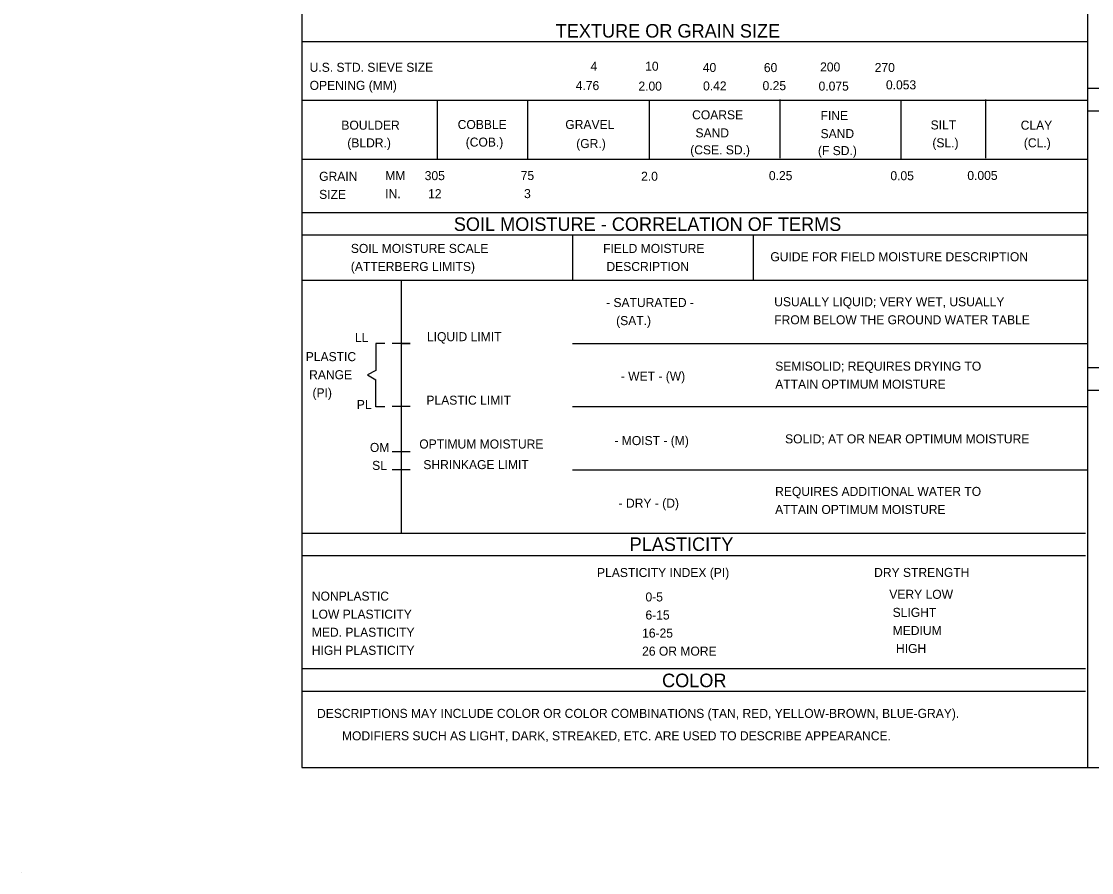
# Model space of a CAD drawing. Extents: x 278710 to 279187, y 171464 to 171625.
# Drawn here: x 278991.9 to 279043.3, y 171480.8 to 171521.6 of the extents above; entities that cross this region are included whole.
import ezdxf

# ---------------------------------------------------------------- set-up
doc = ezdxf.new("R2010")
doc.units = 0
doc.layers.add('Geotech Sheets and Borders Cell', color=7, linetype='Continuous')

msp = doc.modelspace()

# ---------------------------------------------------------------- linework, layer by layer
at = {"layer": 'Geotech Sheets and Borders Cell'}
for p, q in [((279005.33, 171581.203), (279005.33, 171485.806)), ((279043.07, 171566.02), (279043.07, 171485.806)), ((279005.33, 171520.671), (279043.07, 171520.671)), ((279043.07, 171518.437), (279081.678, 171518.437)), ((279005.33, 171517.851), (279043.07, 171517.851)), ((279011.837, 171517.851), (279011.837, 171515.031)), ((279016.175, 171517.851), (279016.175, 171515.031)), ((279022.022, 171517.851), (279022.022, 171515.031)), ((279028.299, 171517.894), (279028.299, 171515.075)), ((279034.108, 171517.851), (279034.108, 171515.031)), ((279038.173, 171517.89), (279038.173, 171515.07)), ((279043.07, 171517.352), (279081.678, 171517.352)), ((279005.33, 171515.031), (279043.07, 171515.031)), ((279005.33, 171512.468), (279043.07, 171512.468)), ((279005.33, 171511.383), (279043.07, 171511.383)), ((279018.344, 171511.383), (279018.344, 171509.214)), ((279027.02, 171511.383), (279027.02, 171509.214)), ((279005.33, 171509.214), (279043.07, 171509.214)), ((279010.101, 171509.214), (279010.101, 171497.068)), ((279010.535, 171506.178), (279009.668, 171506.178)), ((279010.101, 171506.178), (279010.535, 171506.178)), ((279018.344, 171506.178), (279043.07, 171506.178)), ((279121.332, 171505.006), (279043.07, 171505.006)), ((279121.332, 171503.922), (279043.07, 171503.922)), ((279010.535, 171503.141), (279009.668, 171503.141)), ((279018.344, 171503.141), (279043.07, 171503.141)), ((279010.535, 171500.972), (279009.668, 171500.972)), ((279010.535, 171500.104), (279009.668, 171500.104)), ((279018.344, 171500.104), (279043.07, 171500.104)), ((279005.33, 171497.068), (279042.97, 171497.068)), ((279005.33, 171495.983), (279042.97, 171495.983)), ((279005.33, 171490.561), (279042.97, 171490.561)), ((279005.33, 171489.476), (279042.97, 171489.476)), ((279005.33, 171485.806), (279158.027, 171485.806)), ((278991.866, 171480.763), (278991.866, 171480.763))]:
    msp.add_line(p, q, dxfattribs=at)
for points in [[(279009.316, 171506.173), (279008.882, 171506.173), (279008.882, 171504.872)], [(279008.882, 171504.872), (279008.492, 171504.668), (279008.882, 171504.425)], [(279009.316, 171503.124), (279008.882, 171503.124), (279008.882, 171504.425)]]:
    msp.add_lwpolyline(points, dxfattribs=at)

# ---------------------------------------------------------------- texts
for s, height, p in [('TEXTURE OR GRAIN SIZE', 0.6507, (279017.528, 171520.862)), ('U.S. STD. SIEVE SIZE', 0.43381, (279005.711, 171519.218)), ('4    ', 0.4338, (279019.203, 171519.27)), ('10', 0.4338, (279021.827, 171519.27)), (' 40 ', 0.4338, (279024.434, 171519.209)), (' 60   ', 0.4338, (279027.367, 171519.205)), (' 200', 0.4338, (279030.069, 171519.235)), ('   270', 0.4338, (279032.368, 171519.209)), ('OPENING (MM)', 0.43381, (279005.711, 171518.35)), ('4.76   ', 0.4338, (279018.491, 171518.341)), ('2.00', 0.4338, (279021.502, 171518.315)), ('0.42', 0.4338, (279024.608, 171518.324)), ('0.25', 0.4338, (279027.466, 171518.337)), ('0.075', 0.4338, (279030.156, 171518.315)), ('0.053', 0.4338, (279033.392, 171518.376)), ('COARSE', 0.4338, (279024.083, 171516.936)), ('FINE', 0.4338, (279030.251, 171516.901)), ('BOULDER', 0.4338, (279007.234, 171516.437)), ('COBBLE', 0.4338, (279012.821, 171516.472)), ('GRAVEL', 0.4338, (279017.992, 171516.472)), (' SAND', 0.4338, (279024.083, 171516.068)), ('SAND', 0.4338, (279030.251, 171516.033)), ('SILT', 0.4338, (279035.539, 171516.45)), ('CLAY', 0.4338, (279039.864, 171516.437)), ('(BLDR.)', 0.4338, (279007.52, 171515.591)), ('(COB.)', 0.4338, (279013.207, 171515.626)), ('(GR.)', 0.4338, (279018.517, 171515.556)), ('(SL.)', 0.4338, (279035.622, 171515.591)), ('(CL.)', 0.4338, (279040.016, 171515.591)), ('(CSE. SD.)', 0.4338, (279023.992, 171515.253)), ('(F SD.)', 0.4338, (279030.126, 171515.218)), ('GRAIN', 0.4338, (279006.167, 171513.982)), ('MM', 0.4338, (279009.342, 171514.016)), ('305', 0.4338, (279011.238, 171514.016)), ('75', 0.4338, (279015.849, 171514.02)), ('2.0', 0.4338, (279021.632, 171513.986)), ('0.25', 0.4338, (279027.77, 171514.016)), ('0.05', 0.4338, (279033.605, 171514.012)), ('0.005', 0.4338, (279037.301, 171514.025)), ('SIZE', 0.4338, (279006.167, 171513.114)), ('IN.', 0.4338, (279009.342, 171513.149)), (' 12', 0.4338, (279011.238, 171513.149)), (' 3', 0.4338, (279015.849, 171513.153)), ('SOIL MOISTURE - CORRELATION OF TERMS', 0.6507, (279012.635, 171511.578)), ('SOIL MOISTURE SCALE', 0.43381, (279007.69, 171510.52)), ('FIELD MOISTURE', 0.43381, (279019.806, 171510.52)), ('GUIDE FOR FIELD MOISTURE DESCRIPTION', 0.43381, (279027.84, 171510.121)), ('(ATTERBERG LIMITS)', 0.43381, (279007.69, 171509.652)), (' DESCRIPTION', 0.43381, (279019.806, 171509.652)), ('- SATURATED -', 0.43381, (279019.949, 171507.921)), ('USUALLY LIQUID; VERY WET, USUALLY', 0.43381, (279028.026, 171507.96)), ('   (SAT.)', 0.4338, (279019.949, 171507.054)), ('FROM BELOW THE GROUND WATER TABLE', 0.43381, (279028.026, 171507.093)), ('LIQUID LIMIT', 0.43381, (279011.346, 171506.282)), ('LL', 0.4338, (279007.889, 171506.243)), ('PLASTIC', 0.4338, (279005.525, 171505.323)), ('SEMISOLID; REQUIRES DRYING TO', 0.43381, (279028.074, 171504.867)), (' RANGE', 0.4338, (279005.525, 171504.455)), ('- WET - (W)', 0.43381, (279020.656, 171504.386)), ('ATTAIN OPTIMUM MOISTURE', 0.43381, (279028.074, 171504)), ('  (PI)', 0.4338, (279005.525, 171503.588)), ('PLASTIC LIMIT', 0.43381, (279011.32, 171503.232)), ('PL', 0.4338, (279007.976, 171503.024)), ('OPTIMUM MOISTURE', 0.43381, (279010.978, 171501.128)), ('- MOIST - (M)', 0.43381, (279020.348, 171501.293)), ('SOLID; AT OR NEAR OPTIMUM MOISTURE', 0.43381, (279028.547, 171501.375)), ('OM', 0.4338, (279008.605, 171500.963)), ('SL', 0.4338, (279008.713, 171500.1)), ('SHRINKAGE LIMIT', 0.43381, (279011.173, 171500.139)), ('REQUIRES ADDITIONAL WATER TO', 0.43381, (279028.069, 171498.851)), ('- DRY - (D)', 0.43381, (279020.552, 171498.287)), ('ATTAIN OPTIMUM MOISTURE', 0.43381, (279028.069, 171497.983)), ('PLASTICITY', 0.6507, (279021.081, 171496.209)), ('PLASTICITY INDEX (PI)', 0.43381, (279019.515, 171494.955)), ('DRY STRENGTH', 0.43381, (279032.824, 171494.959)), ('NONPLASTIC', 0.4338, (279005.816, 171493.823)), (' 0-5', 0.4338, (279021.68, 171493.784)), ('VERY LOW', 0.4338, (279033.553, 171493.91)), ('LOW PLASTICITY', 0.43381, (279005.816, 171492.955)), (' 6-15', 0.4338, (279021.68, 171492.916)), (' SLIGHT', 0.4338, (279033.553, 171493.042)), ('MED. PLASTICITY', 0.43381, (279005.816, 171492.088)), ('16-25', 0.4338, (279021.68, 171492.049)), (' MEDIUM', 0.4338, (279033.553, 171492.174)), ('HIGH PLASTICITY', 0.43381, (279005.816, 171491.22)), ('26 OR MORE', 0.4338, (279021.68, 171491.181)), ('  HIGH', 0.4338, (279033.553, 171491.307)), ('COLOR', 0.6507, (279022.638, 171489.667)), ('DESCRIPTIONS MAY INCLUDE COLOR OR COLOR COMBINATIONS (TAN, RED, YELLOW-BROWN, BLUE-GRAY).', 0.43381, (279006.066, 171488.192)), ('MODIFIERS SUCH AS LIGHT, DARK, STREAKED, ETC. ARE USED TO DESCRIBE APPEARANCE.', 0.43381, (279007.264, 171487.116))]:
    msp.add_text(s, height=height, dxfattribs=at).set_placement(p)

doc.saveas('drawing.dxf')
